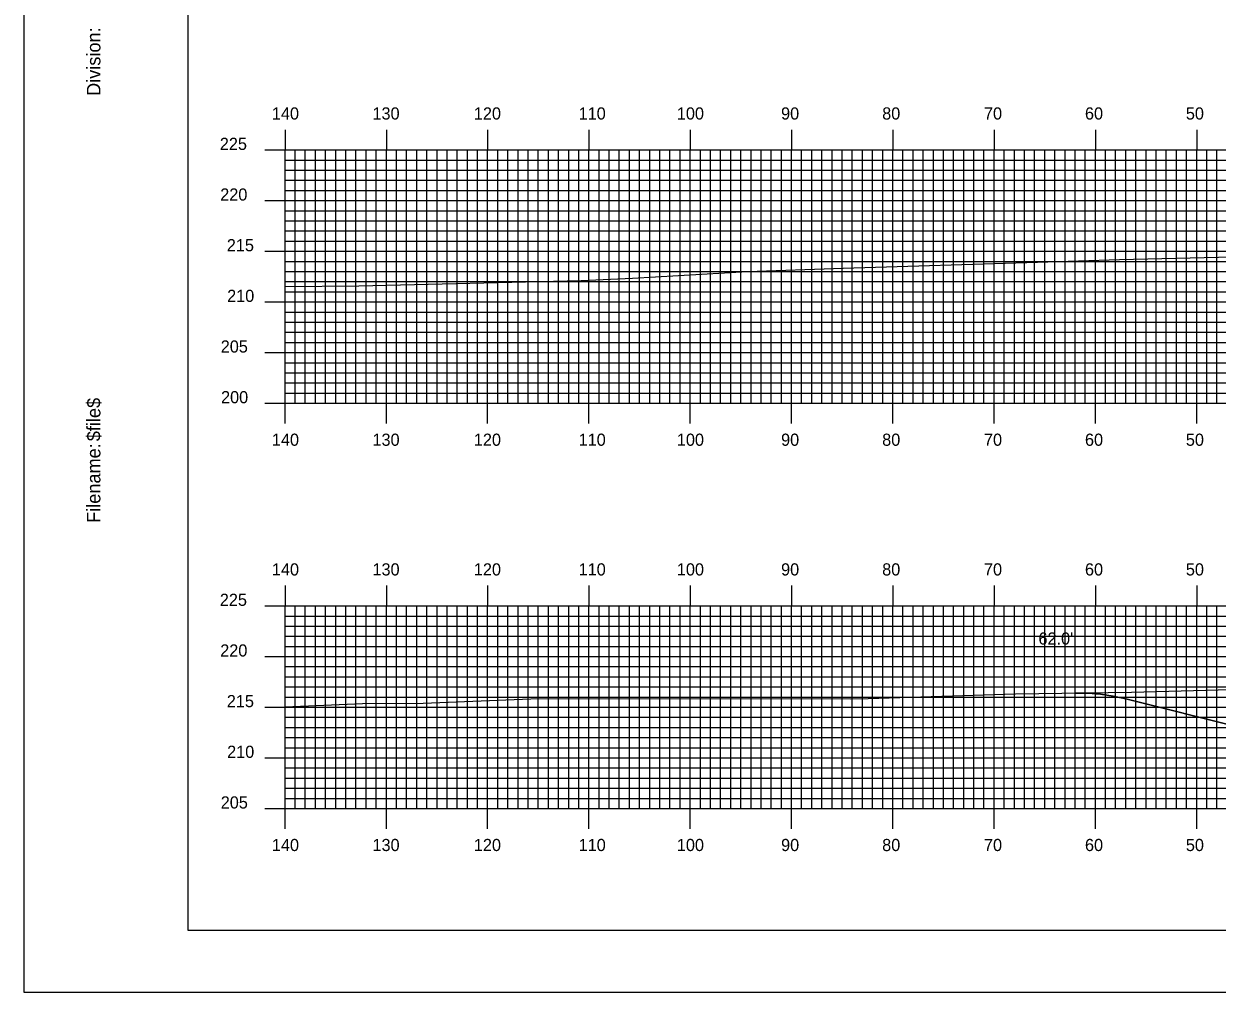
# Model space of a CAD drawing. Extents: x 1821211 to 1821555, y 442591 to 442811.
# Drawn here: x 1821211.4 to 1821329.2, y 442590.5 to 442686.1 of the extents above; entities that cross this region are included whole.
import ezdxf

# ---------------------------------------------------------------- set-up
doc = ezdxf.new("R2010")
doc.units = 0
for name, color, linetype in [('BORDER', 7, 'Continuous'), ('D_Roadway_Centerline', 7, 'Continuous'), ('D_Roadway_SlopeLines', 7, 'Continuous'), ('D_Text_Standard', 7, 'Continuous'), ('H_V ANNOTATION', 7, 'Continuous'), ('MAJOR', 7, 'Continuous'), ('MINOR', 7, 'Continuous'), ('PLOT BOUNDARY', 7, 'Continuous'), ('S_Roadway_Centerline', 7, 'Continuous')]:
    doc.layers.add(name, color=color, linetype=linetype)

msp = doc.modelspace()

# ---------------------------------------------------------------- linework, layer by layer
at = {"layer": 'BORDER'}
msp.add_lwpolyline([(1821227.63, 442596.67), (1821547.63, 442596.67), (1821547.63, 442806.67), (1821227.63, 442806.67)], close=True, dxfattribs=at)
at = {"layer": 'D_Roadway_Centerline'}
msp.add_lwpolyline([(1821315.24, 442620.07), (1821316.49, 442620.04), (1821317.74, 442619.94), (1821318.99, 442619.75), (1821320.24, 442619.48), (1821343.06, 442613.77), (1821347.06, 442614.77), (1821357.23, 442617.32), (1821365.23, 442617.64), (1821377.23, 442617.88), (1821389.23, 442617.64), (1821399.23, 442617.24), (1821409.23, 442614.74), (1821413.23, 442613.74), (1821446.64, 442622.09), (1821447.89, 442622.37), (1821449.14, 442622.58), (1821450.39, 442622.73), (1821451.64, 442622.81)], dxfattribs=at)
at = {"layer": 'D_Roadway_SlopeLines'}
msp.add_lwpolyline([(1821343.06, 442613.77), (1821320.24, 442619.48), (1821318.99, 442619.75), (1821317.74, 442619.94), (1821316.49, 442620.04), (1821315.24, 442620.07)], dxfattribs=at)
at = {"layer": 'MAJOR'}
for p, q in [((1821237.23, 442675.67), (1821237.23, 442673.67)), ((1821247.23, 442675.67), (1821247.23, 442673.67)), ((1821257.23, 442675.67), (1821257.23, 442673.67)), ((1821267.23, 442675.67), (1821267.23, 442673.67)), ((1821277.23, 442675.67), (1821277.23, 442673.67)), ((1821287.23, 442675.67), (1821287.23, 442673.67)), ((1821297.23, 442675.67), (1821297.23, 442673.67)), ((1821307.23, 442675.67), (1821307.23, 442673.67)), ((1821317.23, 442675.67), (1821317.23, 442673.67)), ((1821327.23, 442675.67), (1821327.23, 442673.67)), ((1821235.23, 442673.67), (1821237.23, 442673.67)), ((1821237.23, 442673.67), (1821517.23, 442673.67)), ((1821237.23, 442648.67), (1821237.23, 442673.67)), ((1821237.23, 442648.67), (1821237.23, 442673.67)), ((1821237.23, 442673.67), (1821517.23, 442673.67)), ((1821247.23, 442648.67), (1821247.23, 442673.67)), ((1821257.23, 442648.67), (1821257.23, 442673.67)), ((1821267.23, 442648.67), (1821267.23, 442673.67)), ((1821277.23, 442648.67), (1821277.23, 442673.67)), ((1821287.23, 442648.67), (1821287.23, 442673.67)), ((1821297.23, 442648.67), (1821297.23, 442673.67)), ((1821307.23, 442648.67), (1821307.23, 442673.67)), ((1821317.23, 442648.67), (1821317.23, 442673.67)), ((1821327.23, 442648.67), (1821327.23, 442673.67)), ((1821235.23, 442668.67), (1821237.23, 442668.67)), ((1821237.23, 442668.67), (1821517.23, 442668.67)), ((1821235.23, 442663.67), (1821237.23, 442663.67)), ((1821237.23, 442663.67), (1821517.23, 442663.67)), ((1821235.23, 442658.67), (1821237.23, 442658.67)), ((1821237.23, 442658.67), (1821517.23, 442658.67)), ((1821235.23, 442653.67), (1821237.23, 442653.67)), ((1821237.23, 442653.67), (1821517.23, 442653.67)), ((1821235.23, 442648.67), (1821237.23, 442648.67)), ((1821237.23, 442648.67), (1821517.23, 442648.67)), ((1821237.23, 442648.67), (1821517.23, 442648.67)), ((1821237.23, 442646.66), (1821237.23, 442648.67)), ((1821247.23, 442646.66), (1821247.23, 442648.67)), ((1821257.23, 442646.66), (1821257.23, 442648.67)), ((1821267.23, 442646.66), (1821267.23, 442648.67)), ((1821277.23, 442646.66), (1821277.23, 442648.67)), ((1821287.23, 442646.66), (1821287.23, 442648.67)), ((1821297.23, 442646.66), (1821297.23, 442648.67)), ((1821307.23, 442646.66), (1821307.23, 442648.67)), ((1821317.23, 442646.66), (1821317.23, 442648.67)), ((1821327.23, 442646.66), (1821327.23, 442648.67)), ((1821237.23, 442630.67), (1821237.23, 442628.67)), ((1821247.23, 442630.67), (1821247.23, 442628.67)), ((1821257.23, 442630.67), (1821257.23, 442628.67)), ((1821267.23, 442630.67), (1821267.23, 442628.67)), ((1821277.23, 442630.67), (1821277.23, 442628.67)), ((1821287.23, 442630.67), (1821287.23, 442628.67)), ((1821297.23, 442630.67), (1821297.23, 442628.67)), ((1821307.23, 442630.67), (1821307.23, 442628.67)), ((1821317.23, 442630.67), (1821317.23, 442628.67)), ((1821327.23, 442630.67), (1821327.23, 442628.67)), ((1821235.23, 442628.67), (1821237.23, 442628.67)), ((1821237.23, 442628.67), (1821517.23, 442628.67)), ((1821237.23, 442608.67), (1821237.23, 442628.67)), ((1821237.23, 442608.67), (1821237.23, 442628.67)), ((1821237.23, 442628.67), (1821517.23, 442628.67)), ((1821247.23, 442608.67), (1821247.23, 442628.67)), ((1821257.23, 442608.67), (1821257.23, 442628.67)), ((1821267.23, 442608.67), (1821267.23, 442628.67)), ((1821277.23, 442608.67), (1821277.23, 442628.67)), ((1821287.23, 442608.67), (1821287.23, 442628.67)), ((1821297.23, 442608.67), (1821297.23, 442628.67)), ((1821307.23, 442608.67), (1821307.23, 442628.67)), ((1821317.23, 442608.67), (1821317.23, 442628.67)), ((1821327.23, 442608.67), (1821327.23, 442628.67)), ((1821235.23, 442623.67), (1821237.23, 442623.67)), ((1821237.23, 442623.67), (1821517.23, 442623.67)), ((1821235.23, 442618.67), (1821237.23, 442618.67)), ((1821237.23, 442618.67), (1821517.23, 442618.67)), ((1821235.23, 442613.67), (1821237.23, 442613.67)), ((1821237.23, 442613.67), (1821517.23, 442613.67)), ((1821235.23, 442608.67), (1821237.23, 442608.67)), ((1821237.23, 442608.67), (1821517.23, 442608.67)), ((1821237.23, 442608.67), (1821517.23, 442608.67)), ((1821237.23, 442606.66), (1821237.23, 442608.67)), ((1821247.23, 442606.66), (1821247.23, 442608.67)), ((1821257.23, 442606.66), (1821257.23, 442608.67)), ((1821267.23, 442606.66), (1821267.23, 442608.67)), ((1821277.23, 442606.66), (1821277.23, 442608.67)), ((1821287.23, 442606.66), (1821287.23, 442608.67)), ((1821297.23, 442606.66), (1821297.23, 442608.67)), ((1821307.23, 442606.66), (1821307.23, 442608.67)), ((1821317.23, 442606.66), (1821317.23, 442608.67)), ((1821327.23, 442606.66), (1821327.23, 442608.67))]:
    msp.add_line(p, q, dxfattribs=at)
at = {"layer": 'MINOR'}
for p, q in [((1821237.23, 442672.67), (1821517.23, 442672.67)), ((1821237.23, 442672.67), (1821239.23, 442672.67)), ((1821238.23, 442648.67), (1821238.23, 442673.67)), ((1821239.23, 442648.67), (1821239.23, 442673.67)), ((1821240.23, 442648.67), (1821240.23, 442673.67)), ((1821241.23, 442648.67), (1821241.23, 442673.67)), ((1821242.23, 442648.67), (1821242.23, 442673.67)), ((1821243.23, 442648.67), (1821243.23, 442673.67)), ((1821244.23, 442648.67), (1821244.23, 442673.67)), ((1821245.23, 442648.67), (1821245.23, 442673.67)), ((1821246.23, 442648.67), (1821246.23, 442673.67)), ((1821248.23, 442648.67), (1821248.23, 442673.67)), ((1821249.23, 442648.67), (1821249.23, 442673.67)), ((1821250.23, 442648.67), (1821250.23, 442673.67)), ((1821251.23, 442648.67), (1821251.23, 442673.67)), ((1821252.23, 442648.67), (1821252.23, 442673.67)), ((1821253.23, 442648.67), (1821253.23, 442673.67)), ((1821254.23, 442648.67), (1821254.23, 442673.67)), ((1821255.23, 442648.67), (1821255.23, 442673.67)), ((1821256.23, 442648.67), (1821256.23, 442673.67)), ((1821258.23, 442648.67), (1821258.23, 442673.67)), ((1821259.23, 442648.67), (1821259.23, 442673.67)), ((1821260.23, 442648.67), (1821260.23, 442673.67)), ((1821261.23, 442648.67), (1821261.23, 442673.67)), ((1821262.23, 442648.67), (1821262.23, 442673.67)), ((1821263.23, 442648.67), (1821263.23, 442673.67)), ((1821264.23, 442648.67), (1821264.23, 442673.67)), ((1821265.23, 442648.67), (1821265.23, 442673.67)), ((1821266.23, 442648.67), (1821266.23, 442673.67)), ((1821268.23, 442648.67), (1821268.23, 442673.67)), ((1821269.23, 442648.67), (1821269.23, 442673.67)), ((1821270.23, 442648.67), (1821270.23, 442673.67)), ((1821271.23, 442648.67), (1821271.23, 442673.67)), ((1821272.23, 442648.67), (1821272.23, 442673.67)), ((1821273.23, 442648.67), (1821273.23, 442673.67)), ((1821274.23, 442648.67), (1821274.23, 442673.67)), ((1821275.23, 442648.67), (1821275.23, 442673.67)), ((1821276.23, 442648.67), (1821276.23, 442673.67)), ((1821278.23, 442648.67), (1821278.23, 442673.67)), ((1821279.23, 442648.67), (1821279.23, 442673.67)), ((1821280.23, 442648.67), (1821280.23, 442673.67)), ((1821281.23, 442648.67), (1821281.23, 442673.67)), ((1821282.23, 442648.67), (1821282.23, 442673.67)), ((1821283.23, 442648.67), (1821283.23, 442673.67)), ((1821284.23, 442648.67), (1821284.23, 442673.67)), ((1821285.23, 442648.67), (1821285.23, 442673.67)), ((1821286.23, 442648.67), (1821286.23, 442673.67)), ((1821288.23, 442648.67), (1821288.23, 442673.67)), ((1821289.23, 442648.67), (1821289.23, 442673.67)), ((1821290.23, 442648.67), (1821290.23, 442673.67)), ((1821291.23, 442648.67), (1821291.23, 442673.67)), ((1821292.23, 442648.67), (1821292.23, 442673.67)), ((1821293.23, 442648.67), (1821293.23, 442673.67)), ((1821294.23, 442648.67), (1821294.23, 442673.67)), ((1821295.23, 442648.67), (1821295.23, 442673.67)), ((1821296.23, 442648.67), (1821296.23, 442673.67)), ((1821298.23, 442648.67), (1821298.23, 442673.67)), ((1821299.23, 442648.67), (1821299.23, 442673.67)), ((1821300.23, 442648.67), (1821300.23, 442673.67)), ((1821301.23, 442648.67), (1821301.23, 442673.67)), ((1821302.23, 442648.67), (1821302.23, 442673.67)), ((1821303.23, 442648.67), (1821303.23, 442673.67)), ((1821304.23, 442648.67), (1821304.23, 442673.67)), ((1821305.23, 442648.67), (1821305.23, 442673.67)), ((1821306.23, 442648.67), (1821306.23, 442673.67)), ((1821308.23, 442648.67), (1821308.23, 442673.67)), ((1821309.23, 442648.67), (1821309.23, 442673.67)), ((1821310.23, 442648.67), (1821310.23, 442673.67)), ((1821311.23, 442648.67), (1821311.23, 442673.67)), ((1821312.23, 442648.67), (1821312.23, 442673.67)), ((1821313.23, 442648.67), (1821313.23, 442673.67)), ((1821314.23, 442648.67), (1821314.23, 442673.67)), ((1821315.23, 442648.67), (1821315.23, 442673.67)), ((1821316.23, 442648.67), (1821316.23, 442673.67)), ((1821318.23, 442648.67), (1821318.23, 442673.67)), ((1821319.23, 442648.67), (1821319.23, 442673.67)), ((1821320.23, 442648.67), (1821320.23, 442673.67)), ((1821321.23, 442648.67), (1821321.23, 442673.67)), ((1821322.23, 442648.67), (1821322.23, 442673.67)), ((1821323.23, 442648.67), (1821323.23, 442673.67)), ((1821324.23, 442648.67), (1821324.23, 442673.67)), ((1821325.23, 442648.67), (1821325.23, 442673.67)), ((1821326.23, 442648.67), (1821326.23, 442673.67)), ((1821328.23, 442648.67), (1821328.23, 442673.67)), ((1821329.23, 442648.67), (1821329.23, 442673.67)), ((1821237.23, 442671.67), (1821517.23, 442671.67)), ((1821237.23, 442671.67), (1821239.23, 442671.67)), ((1821237.23, 442670.67), (1821517.23, 442670.67)), ((1821237.23, 442670.67), (1821239.23, 442670.67)), ((1821237.23, 442669.67), (1821517.23, 442669.67)), ((1821237.23, 442669.67), (1821239.23, 442669.67)), ((1821237.23, 442667.67), (1821517.23, 442667.67)), ((1821237.23, 442667.67), (1821239.23, 442667.67)), ((1821237.23, 442666.67), (1821517.23, 442666.67)), ((1821237.23, 442666.67), (1821239.23, 442666.67)), ((1821237.23, 442665.67), (1821517.23, 442665.67)), ((1821237.23, 442665.67), (1821239.23, 442665.67)), ((1821237.23, 442664.67), (1821517.23, 442664.67)), ((1821237.23, 442664.67), (1821239.23, 442664.67)), ((1821237.23, 442662.67), (1821517.23, 442662.67)), ((1821237.23, 442662.67), (1821239.23, 442662.67)), ((1821237.23, 442661.67), (1821517.23, 442661.67)), ((1821237.23, 442661.67), (1821239.23, 442661.67)), ((1821237.23, 442660.67), (1821517.23, 442660.67)), ((1821237.23, 442660.67), (1821239.23, 442660.67)), ((1821237.23, 442659.67), (1821517.23, 442659.67)), ((1821237.23, 442659.67), (1821239.23, 442659.67)), ((1821237.23, 442657.67), (1821517.23, 442657.67)), ((1821237.23, 442657.67), (1821239.23, 442657.67)), ((1821237.23, 442656.67), (1821517.23, 442656.67)), ((1821237.23, 442656.67), (1821239.23, 442656.67)), ((1821237.23, 442655.67), (1821517.23, 442655.67)), ((1821237.23, 442655.67), (1821239.23, 442655.67)), ((1821237.23, 442654.67), (1821517.23, 442654.67)), ((1821237.23, 442654.67), (1821239.23, 442654.67)), ((1821237.23, 442652.67), (1821517.23, 442652.67)), ((1821237.23, 442652.67), (1821239.23, 442652.67)), ((1821237.23, 442651.67), (1821517.23, 442651.67)), ((1821237.23, 442651.67), (1821239.23, 442651.67)), ((1821237.23, 442650.67), (1821517.23, 442650.67)), ((1821237.23, 442650.67), (1821239.23, 442650.67)), ((1821237.23, 442649.67), (1821517.23, 442649.67)), ((1821237.23, 442649.67), (1821239.23, 442649.67)), ((1821238.23, 442608.67), (1821238.23, 442628.67)), ((1821239.23, 442608.67), (1821239.23, 442628.67)), ((1821240.23, 442608.67), (1821240.23, 442628.67)), ((1821241.23, 442608.67), (1821241.23, 442628.67)), ((1821242.23, 442608.67), (1821242.23, 442628.67)), ((1821243.23, 442608.67), (1821243.23, 442628.67)), ((1821244.23, 442608.67), (1821244.23, 442628.67)), ((1821245.23, 442608.67), (1821245.23, 442628.67)), ((1821246.23, 442608.67), (1821246.23, 442628.67)), ((1821248.23, 442608.67), (1821248.23, 442628.67)), ((1821249.23, 442608.67), (1821249.23, 442628.67)), ((1821250.23, 442608.67), (1821250.23, 442628.67)), ((1821251.23, 442608.67), (1821251.23, 442628.67)), ((1821252.23, 442608.67), (1821252.23, 442628.67)), ((1821253.23, 442608.67), (1821253.23, 442628.67)), ((1821254.23, 442608.67), (1821254.23, 442628.67)), ((1821255.23, 442608.67), (1821255.23, 442628.67)), ((1821256.23, 442608.67), (1821256.23, 442628.67)), ((1821258.23, 442608.67), (1821258.23, 442628.67)), ((1821259.23, 442608.67), (1821259.23, 442628.67)), ((1821260.23, 442608.67), (1821260.23, 442628.67)), ((1821261.23, 442608.67), (1821261.23, 442628.67)), ((1821262.23, 442608.67), (1821262.23, 442628.67)), ((1821263.23, 442608.67), (1821263.23, 442628.67)), ((1821264.23, 442608.67), (1821264.23, 442628.67)), ((1821265.23, 442608.67), (1821265.23, 442628.67)), ((1821266.23, 442608.67), (1821266.23, 442628.67)), ((1821268.23, 442608.67), (1821268.23, 442628.67)), ((1821269.23, 442608.67), (1821269.23, 442628.67)), ((1821270.23, 442608.67), (1821270.23, 442628.67)), ((1821271.23, 442608.67), (1821271.23, 442628.67)), ((1821272.23, 442608.67), (1821272.23, 442628.67)), ((1821273.23, 442608.67), (1821273.23, 442628.67)), ((1821274.23, 442608.67), (1821274.23, 442628.67)), ((1821275.23, 442608.67), (1821275.23, 442628.67)), ((1821276.23, 442608.67), (1821276.23, 442628.67)), ((1821278.23, 442608.67), (1821278.23, 442628.67)), ((1821279.23, 442608.67), (1821279.23, 442628.67)), ((1821280.23, 442608.67), (1821280.23, 442628.67)), ((1821281.23, 442608.67), (1821281.23, 442628.67)), ((1821282.23, 442608.67), (1821282.23, 442628.67)), ((1821283.23, 442608.67), (1821283.23, 442628.67)), ((1821284.23, 442608.67), (1821284.23, 442628.67)), ((1821285.23, 442608.67), (1821285.23, 442628.67)), ((1821286.23, 442608.67), (1821286.23, 442628.67)), ((1821288.23, 442608.67), (1821288.23, 442628.67)), ((1821289.23, 442608.67), (1821289.23, 442628.67)), ((1821290.23, 442608.67), (1821290.23, 442628.67)), ((1821291.23, 442608.67), (1821291.23, 442628.67)), ((1821292.23, 442608.67), (1821292.23, 442628.67)), ((1821293.23, 442608.67), (1821293.23, 442628.67)), ((1821294.23, 442608.67), (1821294.23, 442628.67)), ((1821295.23, 442608.67), (1821295.23, 442628.67)), ((1821296.23, 442608.67), (1821296.23, 442628.67)), ((1821298.23, 442608.67), (1821298.23, 442628.67)), ((1821299.23, 442608.67), (1821299.23, 442628.67)), ((1821300.23, 442608.67), (1821300.23, 442628.67)), ((1821301.23, 442608.67), (1821301.23, 442628.67)), ((1821302.23, 442608.67), (1821302.23, 442628.67)), ((1821303.23, 442608.67), (1821303.23, 442628.67)), ((1821304.23, 442608.67), (1821304.23, 442628.67)), ((1821305.23, 442608.67), (1821305.23, 442628.67)), ((1821306.23, 442608.67), (1821306.23, 442628.67)), ((1821308.23, 442608.67), (1821308.23, 442628.67)), ((1821309.23, 442608.67), (1821309.23, 442628.67)), ((1821310.23, 442608.67), (1821310.23, 442628.67)), ((1821311.23, 442608.67), (1821311.23, 442628.67)), ((1821312.23, 442608.67), (1821312.23, 442628.67)), ((1821313.23, 442608.67), (1821313.23, 442628.67)), ((1821314.23, 442608.67), (1821314.23, 442628.67)), ((1821315.23, 442608.67), (1821315.23, 442628.67)), ((1821316.23, 442608.67), (1821316.23, 442628.67)), ((1821318.23, 442608.67), (1821318.23, 442628.67)), ((1821319.23, 442608.67), (1821319.23, 442628.67)), ((1821320.23, 442608.67), (1821320.23, 442628.67)), ((1821321.23, 442608.67), (1821321.23, 442628.67)), ((1821322.23, 442608.67), (1821322.23, 442628.67)), ((1821323.23, 442608.67), (1821323.23, 442628.67)), ((1821324.23, 442608.67), (1821324.23, 442628.67)), ((1821325.23, 442608.67), (1821325.23, 442628.67)), ((1821326.23, 442608.67), (1821326.23, 442628.67)), ((1821328.23, 442608.67), (1821328.23, 442628.67)), ((1821329.23, 442608.67), (1821329.23, 442628.67)), ((1821237.23, 442627.67), (1821517.23, 442627.67)), ((1821237.23, 442627.67), (1821239.23, 442627.67)), ((1821237.23, 442626.67), (1821517.23, 442626.67)), ((1821237.23, 442626.67), (1821239.23, 442626.67)), ((1821237.23, 442625.67), (1821517.23, 442625.67)), ((1821237.23, 442625.67), (1821239.23, 442625.67)), ((1821237.23, 442624.67), (1821517.23, 442624.67)), ((1821237.23, 442624.67), (1821239.23, 442624.67)), ((1821237.23, 442622.67), (1821517.23, 442622.67)), ((1821237.23, 442622.67), (1821239.23, 442622.67)), ((1821237.23, 442621.67), (1821517.23, 442621.67)), ((1821237.23, 442621.67), (1821239.23, 442621.67)), ((1821237.23, 442620.67), (1821517.23, 442620.67)), ((1821237.23, 442620.67), (1821239.23, 442620.67)), ((1821237.23, 442619.67), (1821517.23, 442619.67)), ((1821237.23, 442619.67), (1821239.23, 442619.67)), ((1821237.23, 442617.67), (1821517.23, 442617.67)), ((1821237.23, 442617.67), (1821239.23, 442617.67)), ((1821237.23, 442616.67), (1821517.23, 442616.67)), ((1821237.23, 442616.67), (1821239.23, 442616.67)), ((1821237.23, 442615.67), (1821517.23, 442615.67)), ((1821237.23, 442615.67), (1821239.23, 442615.67)), ((1821237.23, 442614.67), (1821517.23, 442614.67)), ((1821237.23, 442614.67), (1821239.23, 442614.67)), ((1821237.23, 442612.67), (1821517.23, 442612.67)), ((1821237.23, 442612.67), (1821239.23, 442612.67)), ((1821237.23, 442611.67), (1821517.23, 442611.67)), ((1821237.23, 442611.67), (1821239.23, 442611.67)), ((1821237.23, 442610.67), (1821517.23, 442610.67)), ((1821237.23, 442610.67), (1821239.23, 442610.67)), ((1821237.23, 442609.67), (1821517.23, 442609.67)), ((1821237.23, 442609.67), (1821239.23, 442609.67))]:
    msp.add_line(p, q, dxfattribs=at)
at = {"layer": 'PLOT BOUNDARY'}
msp.add_lwpolyline([(1821211.44, 442590.55), (1821551.44, 442590.55), (1821551.44, 442810.55), (1821211.44, 442810.55)], close=True, dxfattribs=at)
at = {"layer": 'S_Roadway_Centerline'}
for points in [[(1821237.23, 442660.18), (1821244.5, 442660.27), (1821266.45, 442660.79), (1821271.53, 442661.03), (1821282.9, 442661.66), (1821292.33, 442661.99), (1821311.5, 442662.6), (1821319.61, 442662.84), (1821333.56, 442663.19)], [(1821237.23, 442618.71), (1821244.89, 442619.03), (1821250.87, 442619.06), (1821261.5, 442619.48), (1821291.26, 442619.52), (1821293.08, 442619.51), (1821294.79, 442619.53), (1821309.34, 442619.98), (1821320.8, 442620.15), (1821334.26, 442620.5)]]:
    msp.add_lwpolyline(points, dxfattribs=at)

# ---------------------------------------------------------------- texts
at = {"layer": 'BORDER'}
for s, p in [('Division:', (1821219, 442679)), ('$file$', (1821219, 442644.92)), ('Filename:', (1821219, 442636.86))]:
    msp.add_text(s, height=1.339, rotation=90, dxfattribs=at).set_placement(p)
at = {"layer": 'D_Text_Standard'}
msp.add_text("62.0'", height=1.2, dxfattribs=at).set_placement((1821311.61, 442624.85))
at = {"layer": 'H_V ANNOTATION'}
for s, p in [('140', (1821235.93, 442676.67)), ('130', (1821245.86, 442676.67)), ('120', (1821255.87, 442676.67)), ('110', (1821266.21, 442676.67)), ('100', (1821275.91, 442676.67)), ('90', (1821286.2, 442676.67)), ('80', (1821296.18, 442676.67)), ('70', (1821306.23, 442676.67)), ('60', (1821316.2, 442676.67)), ('50', (1821326.16, 442676.67)), ('225', (1821230.79, 442673.67)), ('220', (1821230.83, 442668.67)), ('215', (1821231.48, 442663.67)), ('210', (1821231.51, 442658.67)), ('205', (1821230.88, 442653.67)), ('200', (1821230.91, 442648.67)), ('140', (1821235.93, 442644.47)), ('130', (1821245.86, 442644.47)), ('120', (1821255.87, 442644.47)), ('110', (1821266.21, 442644.47)), ('100', (1821275.91, 442644.47)), ('90', (1821286.2, 442644.47)), ('80', (1821296.18, 442644.47)), ('70', (1821306.23, 442644.47)), ('60', (1821316.2, 442644.47)), ('50', (1821326.16, 442644.47)), ('140', (1821235.93, 442631.67)), ('130', (1821245.86, 442631.67)), ('120', (1821255.87, 442631.67)), ('110', (1821266.21, 442631.67)), ('100', (1821275.91, 442631.67)), ('90', (1821286.2, 442631.67)), ('80', (1821296.18, 442631.67)), ('70', (1821306.23, 442631.67)), ('60', (1821316.2, 442631.67)), ('50', (1821326.16, 442631.67)), ('225', (1821230.79, 442628.67)), ('220', (1821230.83, 442623.67)), ('215', (1821231.48, 442618.67)), ('210', (1821231.51, 442613.67)), ('205', (1821230.88, 442608.67)), ('140', (1821235.93, 442604.47)), ('130', (1821245.86, 442604.47)), ('120', (1821255.87, 442604.47)), ('110', (1821266.21, 442604.47)), ('100', (1821275.91, 442604.47)), ('90', (1821286.2, 442604.47)), ('80', (1821296.18, 442604.47)), ('70', (1821306.23, 442604.47)), ('60', (1821316.2, 442604.47)), ('50', (1821326.16, 442604.47))]:
    msp.add_text(s, height=1.2, dxfattribs=at).set_placement(p)
at = {"layer": 'MAJOR'}
for p in [(1821237.22, 442648.67), (1821237.22, 442608.67)]:
    msp.add_text('-', height=0.012, dxfattribs=at).set_placement(p)

doc.saveas('drawing.dxf')
